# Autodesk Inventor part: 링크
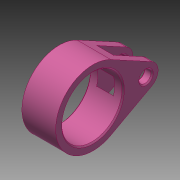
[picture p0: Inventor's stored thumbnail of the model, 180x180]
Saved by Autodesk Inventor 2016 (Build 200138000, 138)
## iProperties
Created: 2016-02
Part Number: 링크
Material: 강철, 연강
Document SubType Name: Modeling
Designer: test
Density: 1 g/cm^3
Appearance: 분홍색
Author: test
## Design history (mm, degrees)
sketch "스케치1"
  geometry: L1 (24.386, 4.394)-(7.398, 13.621); L2 (24.386, -4.394)-(7.398, -13.621); A1 r 15.5 centre (0, 0) between (7.398, 13.621) and (7.398, -13.621); A2 r 5 centre (22, 0) between (24.386, -4.394) and (24.386, 4.394); 1 further point
  constraints: 4 end point, 4 point on circle, 4 tangent, 2 centre point, 1 coincident, 1 horizontal alignment
  dimensions: "d0" = 22 distance of point (0, 0) A2.centre; "d1" = 15.5 radius of A1; "d2" = 5 radius of A2
extrude "돌출1" new body sketch "스케치1" stored distance "d3" = 14; taper "d4" = 0 deg
sketch "스케치2"
  geometry: C1 r 12.5 at (0, 0); 1 further point
  constraints: 1 centre point, 1 coincident
  dimensions: "d5" = 25 diameter of C1
extrude "돌출2" cut sketch "스케치2" stored distance "d6" = 14; taper "d7" = 0 deg
sketch "스케치3"
  geometry: C1 r 2.5 at (22, 0); A1 r 5 centre (22, 0) between (24.386, -4.394) and (24.386, 4.394) reference; 1 further point
  constraints: 1 centre point, 1 coincident
  dimensions: "d8" = 5 diameter of C1
extrude "돌출3" cut sketch "스케치3" stored distance "d9" = 14; taper "d10" = 0 deg
sketch "스케치4"
  geometry: L1 (24.386, -4.394)-(7.398, -13.621) reference; L2 (7.398, 13.621)-(24.386, 4.394) reference; L3 (15, 9.492)-(15, -9.492); C1 r 2.5 at (22, 0) reference; C2 r 12.5 at (0, 0) reference; A1 r 15.5 centre (0, 0) between (7.398, 13.621) and (7.398, -13.621) reference; A2 r 5 centre (22, 0) between (24.386, -4.394) and (24.386, 4.394) reference; 1 further point
  constraints: 2 end point, 2 point on line, 1 vertical
  dimensions: "d11" = 15 distance from line of L3 point (0, 0)
extrude "돌출4" cut sketch "스케치4" stored distance "d12" = 7; taper "d13" = 0 deg
chamfer "모따기1" distance "d14" = 0.5; stored, may be unused: second distance "d15" = 2, angle "d16" = 45 deg
node "솔리드1"
node "절단 모서리 투영1"
